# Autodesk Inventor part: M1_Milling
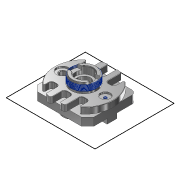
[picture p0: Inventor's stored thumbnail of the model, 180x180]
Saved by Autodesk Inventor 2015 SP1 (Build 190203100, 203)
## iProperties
Created: 2015-04
Part Number: M1_Milling
Material: Alumínio 6061
Document SubType Name: Modeling
Designer: Andrew Almeida
Density: 2.7 g/cm^3
Appearance: Alumínio - Plano
Title: C:/Users/Andrew Almeida/Documents/Projeto WS2015/WS2015 CAD Data ANLAS/07/#07 - CNC Milling/01 - 3D Models/M1_Milling.stp
Creation Date: 2015-04-23
Sending System: Autodesk Translation Framework v4.0.0.5211
Preprocessor: ST-DEVELOPER v16.1
Author: Andrew Almeida
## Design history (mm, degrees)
node "M1_Milling1"
feature "Rosca1" dims "d0" = 10, "d1" = 0
sketch "Esboço2"
  geometry: L1 (21, 0)-(21, 10); L2 (21, 10)-(20.259, 10); L3 (20.259, 10)-(20.259, 0); L4 (20.259, 0)-(21, 0); L5 (0, -11.3)-(0, 53.8) reference
  constraints: 8 end point
revolve "Revolução1" sketch "Esboço2" stored, may be unused: angle "d11" = 0 deg
sketch "Esboço3"
  geometry: L1 (21, 0)-(21, 10); L2 (21, 10)-(20.259, 10); L3 (20.259, 10)-(20.259, 0); L4 (20.259, 0)-(21, 0); L5 (0, -11.3)-(0, 53.8) reference
  constraints: 8 end point
revolve "Revolução2" sketch "Esboço3" stored, may be unused: angle "d12" = 0 deg
sketch "Esboço1"
  geometry: L1 (-0.583, -20.309)-(-0.5, -20.309); L2 (0.083, -20.95)-(0, -21.11); L3 (-1, -21.11)-(-1.083, -20.95); L4 (-0.417, -20.309)-(-0.5, -20.149); L5 (-0.5, -20.149)-(-0.583, -20.309); L6 (-1, -21.11)-(-0.917, -20.95); L7 (-0.417, -20.309)-(-0.083, -20.95); L8 (-1.083, -20.95)-(-0.917, -20.95); L9 (0.083, -20.95)-(-0.083, -20.95); L10 (-1, -21.11)-(-1, -20.95); L11 (0, -21.11)-(0, -20.95); L12 (-0.5, -20.149)-(-0.5, -20.259); L13 (-1, -21)-(0, -21); L14 (-0.083, -20.95)-(0, -21.11); L15 (-0.917, -20.95)-(-0.583, -20.309); L16 (0, 0)-(0, 0.018); L17 (0, 0.018)-(0, 0); L18 (0, 0)-(0.033, 0); L19 (-0.5, -20.259)-(-0.5, -20.309); L20 (-0.5, -20.309)-(-0.417, -20.309); A1 r 0.094 centre (-1, -20.906) between (-1.083, -20.95) and (-1, -21); A2 r 0.094 centre (-1, -20.906) between (-1, -21) and (-0.917, -20.95); A3 r 0.094 centre (0, -20.906) between (-0.083, -20.95) and (0, -21); A4 r 0.094 centre (0, -20.906) between (0, -21) and (0.083, -20.95); A5 r 0.094 centre (-0.5, -20.353) between (-0.5, -20.259) and (-0.583, -20.309); A6 r 0.094 centre (-0.5, -20.353) between (-0.417, -20.309) and (-0.5, -20.259)
  constraints: 40 end point, 12 point on circle, 10 parallel, 8 tangent, 6 centre point, 6 collinear, 2 midpoint, 2 point on line, 1 horizontal, 1 perpendicular, 3 other
  dimensions: "d2" = 55 deg angle of L7 L15 (= d9); "d3" = 0.16008 distance of L4.end L1.end (= 0.160083 x Esboço1_Pitch); "d4" = 0.16008 distance of L2.end L11.end (= 0.160083 x Esboço1_Pitch); "Esboço1_ThreadOffset" = 0 distance between parallel lines of L16 L11; "Esboço1_MajorRadius" = 21 distance from line of L13 L16.start; "d7" = 1 distance from line of L2.end L10 (= Esboço1_Pitch); "Esboço1_MinorRadius" = 20.25854 distance edge to line of A6 L18 (derived)
feature "Espiral1" sketch "Esboço1" pitch "d13" = 1.5015; turns "d15" = 1; dims "d14" = 13, "d16" = 0, angle "d17" = 0 deg, angle "d18" = 0 deg, "d19" = 0, "d20" = 0
feature "Rosca2" dims "d21" = 10, "d22" = 0
sketch "Esboço5"
  geometry: L1 (2.458, 0)-(2.458, 14.1); L2 (2.458, 14.1)-(1.717, 14.1); L3 (1.717, 14.1)-(1.717, 0); L4 (1.717, 0)-(2.458, 0); L5 (0, -27.3)-(0, 37.8) reference
  constraints: 8 end point
revolve "Revolução3" sketch "Esboço5" stored, may be unused: angle "d32" = 0 deg
sketch "Esboço4"
  geometry: L1 (-0.583, -0.051)-(-0.5, -0.051); L2 (0.083, -0.691)-(0, -0.851); L3 (-1, -0.851)-(-1.083, -0.691); L4 (-0.417, -0.051)-(-0.5, 0.109); L5 (-0.5, 0.109)-(-0.583, -0.051); L6 (-1, -0.851)-(-0.917, -0.691); L7 (-0.417, -0.051)-(-0.083, -0.691); L8 (-1.083, -0.691)-(-0.917, -0.691); L9 (0.083, -0.691)-(-0.083, -0.691); L10 (-1, -0.851)-(-1, -0.691); L11 (0, -0.851)-(0, -0.691); L12 (-0.5, 0.109)-(-0.5, 0); L13 (-1, -0.742)-(0, -0.742); L14 (-0.083, -0.691)-(0, -0.851); L15 (-0.917, -0.691)-(-0.583, -0.051); L16 (0, 0)-(0, 0.018); L17 (0, 0.018)-(0, 0); L18 (0, 0)-(0.033, 0); L19 (-0.5, 0)-(-0.5, -0.051); L20 (-0.5, -0.051)-(-0.417, -0.051); A1 r 0.094 centre (-1, -0.648) between (-1.083, -0.691) and (-1, -0.742); A2 r 0.094 centre (-1, -0.648) between (-1, -0.742) and (-0.917, -0.691); A3 r 0.094 centre (0, -0.648) between (-0.083, -0.691) and (0, -0.742); A4 r 0.094 centre (0, -0.648) between (0, -0.742) and (0.083, -0.691); A5 r 0.094 centre (-0.5, -0.094) between (-0.5, 0) and (-0.583, -0.051); A6 r 0.094 centre (-0.5, -0.094) between (-0.417, -0.051) and (-0.5, 0)
  constraints: 40 end point, 12 point on circle, 10 parallel, 8 tangent, 6 centre point, 6 collinear, 2 midpoint, 2 point on line, 1 horizontal, 1 perpendicular, 3 other
  dimensions: "d23" = 55 deg angle of L7 L15 (= d30); "d24" = 0.16008 distance of L4.end L1.end (= 0.160083 x Esboço4_Pitch); "d25" = 0.16008 distance of L2.end L11.end (= 0.160083 x Esboço4_Pitch); "Esboço4_ThreadOffset" = 0 distance between parallel lines of L16 L11; "Esboço4_MajorRadius" = 0.74146 distance from line of L13 L16.start; "d28" = 1 distance from line of L2.end L10 (= Esboço4_Pitch); "Esboço4_MinorRadius" = 0 distance edge to line of A6 L18 (derived)
feature "Espiral2" sketch "Esboço4" pitch "d33" = 1.001; turns "d35" = 1; dims "d34" = 16.1, "d36" = 0, angle "d37" = 0 deg, angle "d38" = 0 deg, "d39" = 0, "d40" = 0
sketch "Sketch6"
  geometry: L1 (-12, 0)-(88, 0); L2 (88, 0)-(88, -80); L3 (88, -80)-(-12, -80); L4 (-12, -80)-(-12, 0); L5 (-12, 0)-(88, -80); L6 (88, 0)-(-12, -80); L7 (68.5, -23)-(24, -23) reference; L8 (73.5, -51)-(73.5, -28) reference; L9 (24, -23)-(24, -59.5) reference; L10 (53, -59.5)-(53, -56) reference; L11 (58, -51)-(73.5, -51) reference; A1 r 5 centre (68.5, -28) between (73.5, -28) and (68.5, -23) reference; A2 r 14.5 centre (38.5, -59.5) between (24, -59.5) and (53, -59.5) reference; A3 r 5 centre (58, -56) between (58, -51) and (53, -56) reference; 1 further point
  constraints: 12 end point, 2 midpoint, 2 parallel, 1 horizontal, 1 perpendicular
  dimensions: "d43" = 100 distance of L2.end L3.end; "d44" = 80 distance of L1.end L2.end
node "Body1"
node "Base1"
node "Sólido2"
node "Sólido3"
other parameters: "d9" = 55 deg [user parameter; used in 1 equation term], "Esboço1_Pitch" = 1 [user parameter; used in 3 equation terms], "d30" = 55 deg [user parameter; used in 1 equation term], "Esboço4_Pitch" = 1 [user parameter; used in 3 equation terms]
